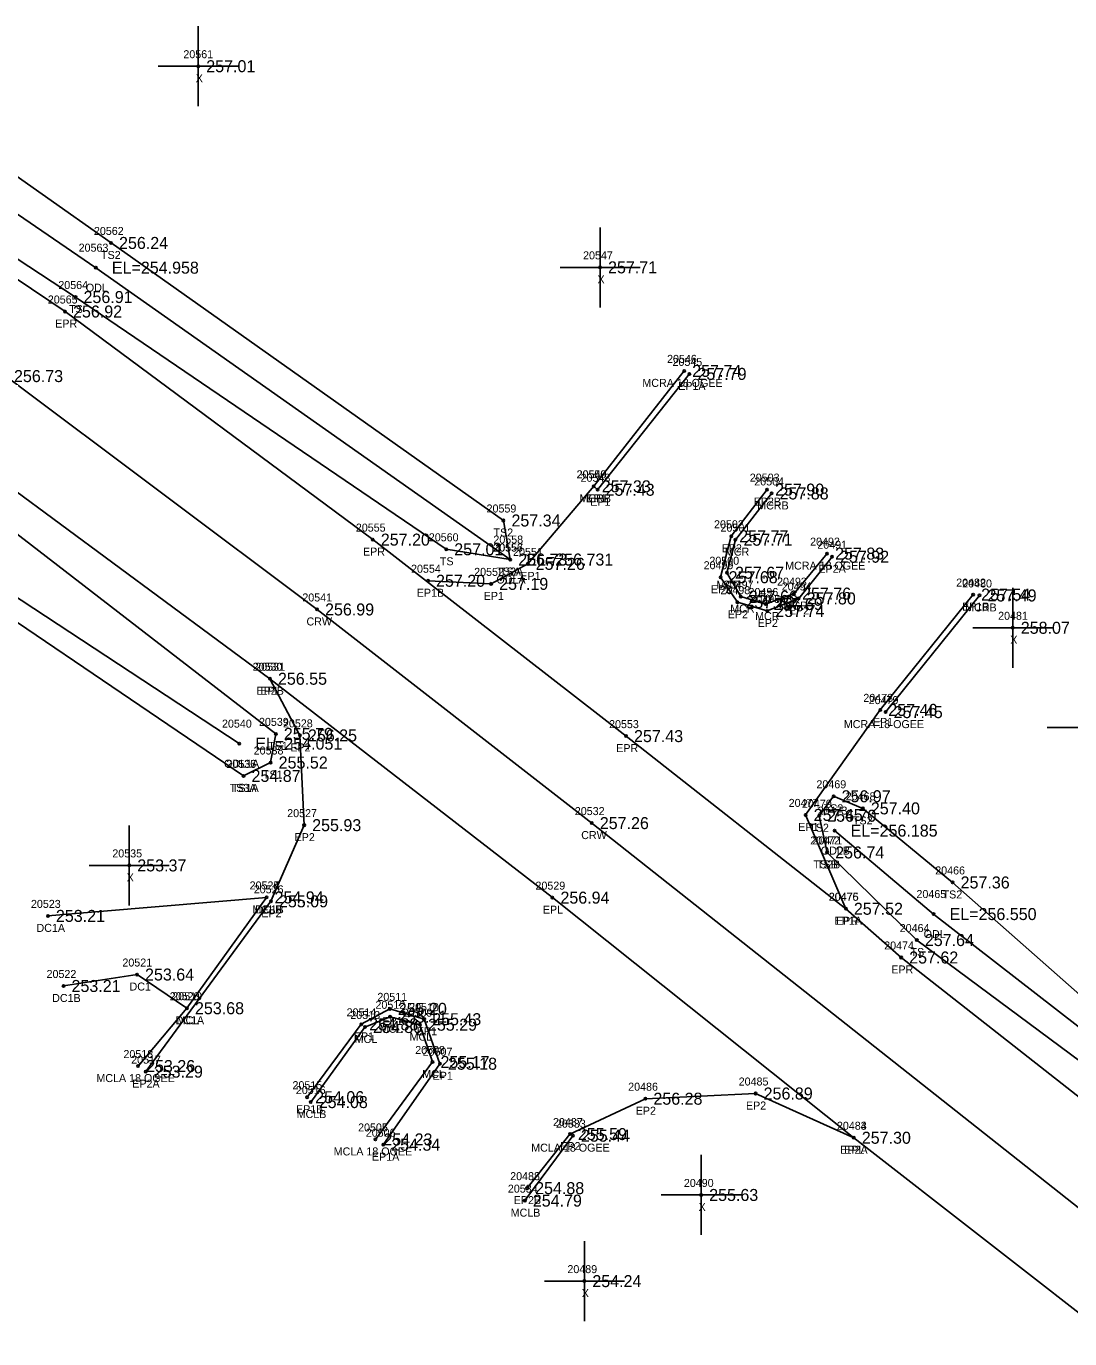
# Model space of a CAD drawing. Extents: x 1961330 to 1962287, y 800294 to 801079.
# Drawn here: x 1961401.6 to 1961532, y 800892.8 to 801056.9 of the extents above; entities that cross this region are included whole.
import ezdxf

# ---------------------------------------------------------------- set-up
doc = ezdxf.new("R2010")
doc.units = 0
for name, color, linetype in [('RD_DTM_BkLn1', 7, 'Continuous'), ('RD_DTM_BkLn2', 7, 'Continuous'), ('RD_DTM_BkLn_txCode', 7, 'Continuous'), ('RD_EX_Conc', 7, 'Continuous'), ('RD_EX_Conc_txCode', 7, 'Continuous'), ('RD_EX_H2O', 7, 'Continuous'), ('RD_EX_H2O_txCode', 7, 'Continuous'), ('RD_EX_Misc', 7, 'Continuous'), ('RD_EX_Misc_txCode', 7, 'Continuous'), ('RD_EX_Road', 7, 'Continuous'), ('RD_EX_Road_txCode', 7, 'Continuous'), ('RD_EX_TX_Conc_ELEV', 7, 'Continuous'), ('RD_EX_TX_H2O_ELEV', 7, 'Continuous'), ('RD_EX_TX_Misc_ELEV', 7, 'Continuous'), ('RD_EX_TX_Road_ELEV', 7, 'Continuous'), ('RD_HC_Survey_ELEV', 7, 'Continuous'), ('RD_HC_Survey_txCode', 7, 'Continuous'), ('RD_SMD_Locator', 7, 'Continuous')]:
    doc.layers.add(name, color=color, linetype=linetype)

msp = doc.modelspace()

# ---------------------------------------------------------------- linework, layer by layer
at = {"layer": 'RD_DTM_BkLn1'}
msp.add_lwpolyline([(1962257.08, 800334.72), (1962203.79, 800372.43), (1962164.31, 800399.58), (1962126.58, 800429.85), (1962084.5, 800463.37), (1962045.12, 800502.48), (1962010.49, 800530.36), (1961971.27, 800562.01), (1961931.18, 800594.14), (1961890.91, 800625.98), (1961844.41, 800662.62), (1961808.07, 800691.13), (1961729.11, 800753.37), (1961696.19, 800780.32), (1961667.25, 800802.66), (1961624.93, 800836.78), (1961588.01, 800866), (1961545.37, 800899.49), (1961472.25, 800957.29), (1961437.91, 800983.99), (1961399.03, 801013.16), (1961365.01, 801035.89)], dxfattribs=at)
at = {"layer": 'RD_DTM_BkLn2'}
for points in [[(1961462.06, 800990.23), (1961461.21, 800995.11), (1961412.16, 801029.8), (1961377.62, 801054.15)], [(1961462.06, 800990.23), (1961454.06, 800991.51), (1961407.72, 801023.04), (1961372.82, 801045.93)], [(1961428.72, 800963.19), (1961432.11, 800964.86), (1961432.76, 800968.44), (1961389.94, 801001.5), (1961357.87, 801022.45)], [(1961428.72, 800963.19), (1961383.97, 800993.54), (1961351.89, 801014.62)], [(1961558.68, 800914.76), (1961539.94, 800929.91), (1961517.35, 800949.87), (1961506.13, 800959.13), (1961502.47, 800960.64), (1961500.68, 800958.21), (1961501.67, 800953.62)], [(1961558.68, 800914.76), (1961535.94, 800925.53), (1961512.88, 800942.67), (1961501.67, 800953.62)]]:
    msp.add_lwpolyline(points, dxfattribs=at)
at = {"layer": 'RD_EX_Conc'}
for p, q in [((1961483.8, 801013.81), (1961472.49, 800999.38)), ((1961508.98, 800971.16), (1961520.71, 800985.74)), ((1961404.27, 800945.69), (1961431.6, 800948)), ((1961469.89, 800918.22), (1961463.88, 800910.1))]:
    msp.add_line(p, q, dxfattribs=at)
for points in [[(1961501.66, 800990.97), (1961497.53, 800985.97), (1961493.98, 800984.67), (1961490.87, 800985.6), (1961489.15, 800988.58), (1961490.21, 800992.71), (1961494.72, 800998.49)], [(1961415.54, 800926.92), (1961421.65, 800934.15), (1961431.6, 800948)], [(1961421.65, 800934.15), (1961415.41, 800938.36), (1961406.22, 800936.93)], [(1961445.2, 800917.75), (1961452.34, 800927.43), (1961450.77, 800932.09), (1961447.04, 800933.08), (1961443.9, 800931.8), (1961437.12, 800922.42)]]:
    msp.add_lwpolyline(points, dxfattribs=at)
at = {"layer": 'RD_EX_H2O'}
for points in [[(1961462.06, 800990.23), (1961410.26, 801026.71), (1961375.03, 801050.82)], [(1961428.19, 800967.22), (1961385.82, 800995.06), (1961353.46, 801018.5)], [(1961558.68, 800914.76), (1961538.2, 800927.85), (1961514.97, 800945.92), (1961502.6, 800956.35)]]:
    msp.add_lwpolyline(points, dxfattribs=at)
at = {"layer": 'RD_EX_Misc'}
for p, q in [((1961423.06, 801046.89), (1961423.06, 801056.89)), ((1961418.06, 801051.89), (1961428.06, 801051.89)), ((1961473.28, 801021.75), (1961473.28, 801031.75)), ((1961468.28, 801026.75), (1961478.28, 801026.75)), ((1961524.87, 800976.7), (1961524.87, 800986.7)), ((1961519.87, 800981.7), (1961529.87, 800981.7)), ((1961529.15, 800969.23), (1961539.15, 800969.23)), ((1961414.44, 800947), (1961414.44, 800957)), ((1961409.44, 800952), (1961419.44, 800952)), ((1961485.92, 800905.81), (1961485.92, 800915.81)), ((1961480.92, 800910.81), (1961490.92, 800910.81)), ((1961471.32, 800895.04), (1961471.32, 800905.04)), ((1961466.32, 800900.04), (1961476.32, 800900.04))]:
    msp.add_line(p, q, dxfattribs=at)
at = {"layer": 'RD_EX_Road'}
for points in [[(1961651.45, 800830.73), (1961641.14, 800839.02), (1961595.18, 800874.45), (1961552.9, 800907.54), (1961510.92, 800940.49), (1961504.01, 800946.58), (1961476.53, 800968.16), (1961444.88, 800992.72), (1961406.41, 801021.23), (1961370.69, 801045.26)], [(1961660.52, 800795.31), (1961637.49, 800813.67), (1961617.86, 800829), (1961581.48, 800857.91), (1961538.42, 800891.96), (1961505, 800917.96), (1961467.33, 800947.97), (1961432.02, 800975.33), (1961392.71, 801004.33), (1961360.06, 801026.78)], [(1961484.46, 801013.43), (1961472.97, 800998.95), (1961472.49, 800999.38), (1961464.24, 800989.69), (1961459.67, 800987.19), (1961451.78, 800987.58)], [(1961502.28, 800990.58), (1961498.11, 800985.37), (1961494.19, 800983.8), (1961490.45, 800984.9), (1961488.35, 800988.02), (1961489.68, 800993.14), (1961494.16, 800998.97)], [(1961504.01, 800946.58), (1961498.98, 800958.31), (1961508.31, 800971.44), (1961519.92, 800985.85)], [(1961416.5, 800926.22), (1961432.15, 800947.51), (1961436.3, 800957.03), (1961435.77, 800968.25), (1961432.02, 800975.33)], [(1961446.18, 800917.09), (1961453.27, 800927.21), (1961451.3, 800932.78), (1961447, 800934.07), (1961443.43, 800932.14), (1961436.67, 800923.03)], [(1961505, 800917.96), (1961492.73, 800923.49), (1961478.95, 800922.84), (1961469.51, 800918.42), (1961464.17, 800911.66)]]:
    msp.add_lwpolyline(points, dxfattribs=at)
at = {"layer": 'RD_SMD_Locator'}
for centre in [(1961423.06, 801051.89), (1961412.16, 801029.8), (1961410.26, 801026.71), (1961473.28, 801026.75), (1961407.72, 801023.04), (1961406.41, 801021.23), (1961483.8, 801013.81), (1961484.46, 801013.43), (1961472.49, 800999.38), (1961472.49, 800999.38), (1961472.97, 800998.95), (1961494.16, 800998.97), (1961494.72, 800998.49), (1961461.21, 800995.11), (1961444.88, 800992.72), (1961489.68, 800993.14), (1961490.21, 800992.71), (1961454.06, 800991.51), (1961462.06, 800990.23), (1961462.06, 800990.23), (1961462.06, 800990.23), (1961501.66, 800990.97), (1961502.28, 800990.58), (1961464.24, 800989.69), (1961489.15, 800988.58), (1961451.78, 800987.58), (1961459.67, 800987.19), (1961488.35, 800988.02), (1961490.87, 800985.6), (1961497.53, 800985.97), (1961498.11, 800985.37), (1961519.92, 800985.85), (1961520.71, 800985.74), (1961437.91, 800983.99), (1961490.45, 800984.9), (1961493.98, 800984.67), (1961494.19, 800983.8), (1961524.87, 800981.7), (1961432.02, 800975.33), (1961432.02, 800975.33), (1961508.31, 800971.44), (1961508.98, 800971.16), (1961428.19, 800967.22), (1961432.76, 800968.44), (1961435.77, 800968.25), (1961476.53, 800968.16), (1961432.11, 800964.86), (1961428.72, 800963.19), (1961428.72, 800963.19), (1961502.47, 800960.64), (1961506.13, 800959.13), (1961472.25, 800957.29), (1961498.98, 800958.31), (1961500.68, 800958.21), (1961436.3, 800957.03), (1961502.6, 800956.35), (1961501.67, 800953.62), (1961501.67, 800953.62), (1961414.44, 800952), (1961517.35, 800949.87), (1961431.6, 800948), (1961431.6, 800948), (1961432.15, 800947.51), (1961467.33, 800947.97), (1961504.01, 800946.58), (1961504.01, 800946.58), (1961514.97, 800945.92), (1961404.27, 800945.69), (1961512.88, 800942.67), (1961510.92, 800940.49), (1961415.41, 800938.36), (1961406.22, 800936.93), (1961421.65, 800934.15), (1961421.65, 800934.15), (1961447, 800934.07), (1961447.04, 800933.08), (1961451.3, 800932.78), (1961443.43, 800932.14), (1961443.9, 800931.8), (1961450.77, 800932.09), (1961415.54, 800926.92), (1961416.5, 800926.22), (1961452.34, 800927.43), (1961453.27, 800927.21), (1961436.67, 800923.03), (1961478.95, 800922.84), (1961492.73, 800923.49), (1961437.12, 800922.42), (1961469.51, 800918.42), (1961469.89, 800918.22), (1961505, 800917.96), (1961505, 800917.96), (1961445.2, 800917.75), (1961446.18, 800917.09), (1961464.17, 800911.66), (1961463.88, 800910.1), (1961485.92, 800910.81), (1961471.32, 800900.04)]:
    msp.add_circle(centre, 0.15, dxfattribs=at)

# ---------------------------------------------------------------- texts
at = {"layer": 'RD_DTM_BkLn_txCode'}
for s, p in [('20562', (1961410.02, 801030.8)), ('TS2', (1961410.91, 801027.8)), ('20564', (1961405.57, 801024.04)), ('TS', (1961406.92, 801021.04)), ('20559', (1961459.1, 800996.11)), ('20560', (1961451.88, 800992.51)), ('TS2', (1961459.97, 800993.11)), ('20556', (1961459.92, 800991.23)), ('20557', (1961459.95, 800991.23)), ('TS', (1961453.26, 800989.51)), ('TS2A', (1961460.33, 800988.23)), ('TSA', (1961460.78, 800988.23)), ('20539', (1961430.65, 800969.44)), ('TS1', (1961431.8, 800966.44)), ('20538', (1961429.99, 800965.86)), ('20536', (1961426.58, 800964.19)), ('20537', (1961426.6, 800964.19)), ('TS1', (1961431.15, 800962.86)), ('20469', (1961500.33, 800961.64)), ('TS3A', (1961426.99, 800961.19)), ('TS1A', (1961427.27, 800961.19)), ('20468', (1961503.99, 800960.13)), ('20470', (1961498.52, 800959.21)), ('TS2', (1961501.23, 800958.64)), ('TS2', (1961504.89, 800957.13)), ('TS2', (1961499.43, 800956.21)), ('20472', (1961499.55, 800954.62)), ('20471', (1961499.83, 800954.62)), ('TS2B', (1961499.95, 800951.62)), ('TSB', (1961500.4, 800951.62)), ('20466', (1961515.18, 800950.87)), ('TS2', (1961516.1, 800947.87)), ('20464', (1961510.74, 800943.67)), ('TS', (1961512.09, 800940.67))]:
    msp.add_text(s, height=1, dxfattribs=at).set_placement(p)
at = {"layer": 'RD_EX_Conc_txCode'}
for s, p in [('20546', (1961481.66, 801014.81)), ('MCRA 18 OGEE', (1961478.57, 801011.81)), ('20549', (1961470.37, 801000.38)), ('20504', (1961492.56, 800999.49)), ('MCRB', (1961470.71, 800997.38)), ('MCRB', (1961492.93, 800996.49)), ('20501', (1961488.34, 800993.71)), ('20492', (1961499.54, 800991.97)), ('20500', (1961486.95, 800989.58)), ('MCR', (1961488.89, 800990.71)), ('MCRA 18 OGEE', (1961496.42, 800988.97)), ('MCR', (1961487.83, 800986.58)), ('20497', (1961488.75, 800986.6)), ('20493', (1961495.41, 800986.97)), ('20480', (1961518.55, 800986.74)), ('20496', (1961491.84, 800985.67)), ('MCR', (1961489.56, 800983.6)), ('MCR', (1961492.66, 800982.67)), ('MCR', (1961496.21, 800983.97)), ('MCRB', (1961518.92, 800983.74)), ('20479', (1961506.86, 800972.16)), ('MCRA 18 OGEE', (1961503.75, 800969.16)), ('20524', (1961429.48, 800949)), ('20525', (1961429.48, 800949)), ('20523', (1961402.15, 800946.69)), ('MCLB', (1961429.83, 800946)), ('DC1B', (1961430.18, 800946)), ('DC1A', (1961402.84, 800943.69)), ('20521', (1961413.58, 800939.36)), ('20522', (1961404.1, 800937.93)), ('DC1', (1961414.47, 800936.36)), ('20520', (1961419.5, 800935.15)), ('20519', (1961419.82, 800935.15)), ('DC1B', (1961404.8, 800934.93)), ('20512', (1961445.21, 800934.08)), ('DC1A', (1961420.22, 800932.15)), ('MCL', (1961420.36, 800932.15)), ('20513', (1961442.07, 800932.8)), ('20509', (1961448.61, 800933.09)), ('MCL', (1961445.75, 800931.08)), ('MCL', (1961442.61, 800929.8)), ('MCL', (1961449.48, 800930.09)), ('20518', (1961413.71, 800927.92)), ('20508', (1961450.18, 800928.43)), ('MCL', (1961451.05, 800925.43)), ('MCLA 18 OGEE', (1961410.33, 800924.92)), ('20516', (1961435.26, 800923.42)), ('MCLB', (1961435.36, 800920.42)), ('20505', (1961443.04, 800918.75)), ('20533', (1961467.77, 800919.22)), ('MCLA 18 OGEE', (1961439.99, 800915.75)), ('MCLA 18 OGEE', (1961464.68, 800916.22)), ('20534', (1961461.76, 800911.1)), ('MCLB', (1961462.11, 800908.1))]:
    msp.add_text(s, height=1, dxfattribs=at).set_placement(p)
at = {"layer": 'RD_EX_H2O_txCode'}
for s, p in [('20563', (1961408.11, 801028.71)), ('ODL', (1961409.01, 801023.71)), ('20558', (1961459.95, 800992.23)), ('ODLA', (1961460.33, 800987.23)), ('20540', (1961426.03, 800969.22)), ('ODL1A', (1961426.29, 800964.22)), ('20473', (1961500.48, 800958.35)), ('ODLB', (1961500.88, 800953.35)), ('20465', (1961512.83, 800947.92)), ('ODL', (1961513.73, 800942.92))]:
    msp.add_text(s, height=1, dxfattribs=at).set_placement(p)
at = {"layer": 'RD_EX_Misc_txCode'}
for s, p in [('20561', (1961421.2, 801052.89)), ('X', (1961422.75, 801049.89)), ('20547', (1961471.16, 801027.75)), ('X', (1961472.96, 801024.75)), ('20481', (1961523.04, 800982.7)), ('X', (1961524.56, 800979.7)), ('20535', (1961412.32, 800953)), ('X', (1961414.12, 800950)), ('20490', (1961483.76, 800911.81)), ('X', (1961485.6, 800908.81)), ('20489', (1961469.2, 800901.04)), ('X', (1961471, 800898.04))]:
    msp.add_text(s, height=1, dxfattribs=at).set_placement(p)
at = {"layer": 'RD_EX_Road_txCode'}
for s, p in [('20565', (1961404.26, 801022.23)), ('EPR', (1961405.18, 801019.23)), ('20545', (1961482.34, 801014.43)), ('EP1A', (1961483.05, 801011.43)), ('20550', (1961470.34, 801000.38)), ('20548', (1961470.85, 800999.95)), ('20503', (1961492, 800999.97)), ('EP1', (1961471.57, 800997.38)), ('EP1', (1961472.05, 800996.95)), ('EP2B', (1961492.48, 800996.97)), ('20502', (1961487.53, 800994.14)), ('20555', (1961442.76, 800993.72)), ('EP2', (1961488.48, 800991.14)), ('20491', (1961500.44, 800991.58)), ('EPR', (1961443.65, 800990.72)), ('20551', (1961462.41, 800990.69)), ('20554', (1961449.66, 800988.58)), ('20552', (1961457.55, 800988.19)), ('EP1', (1961463.32, 800987.69)), ('20499', (1961486.23, 800989.02)), ('EP2A', (1961500.58, 800988.58)), ('EP2', (1961487.14, 800986.02)), ('20494', (1961495.99, 800986.37)), ('20482', (1961517.8, 800986.85)), ('EP1B', (1961450.38, 800985.58)), ('EP1', (1961458.74, 800985.19)), ('20498', (1961488.33, 800985.9)), ('20495', (1961492.07, 800984.8)), ('EP2', (1961489.25, 800982.9)), ('EP2', (1961496.9, 800983.37)), ('EP1B', (1961518.53, 800983.85)), ('EP2', (1961492.98, 800981.8)), ('20530', (1961429.86, 800976.33)), ('20531', (1961430.19, 800976.33)), ('EP2B', (1961430.34, 800973.33)), ('EPL', (1961430.82, 800973.33)), ('20478', (1961506.19, 800972.44)), ('20528', (1961433.65, 800969.25)), ('20553', (1961474.41, 800969.16)), ('EP1', (1961507.39, 800969.44)), ('EP2', (1961434.57, 800966.25)), ('EPR', (1961475.3, 800966.16)), ('20477', (1961496.86, 800959.31)), ('20527', (1961434.18, 800958.03)), ('EP2', (1961435.1, 800955.03)), ('EP1', (1961498.06, 800956.31)), ('20526', (1961430, 800948.51)), ('20529', (1961465.21, 800948.97)), ('20476', (1961501.86, 800947.58)), ('20475', (1961501.89, 800947.58)), ('EP2', (1961430.94, 800945.51)), ('EPL', (1961466.13, 800945.97)), ('EP1A', (1961502.6, 800944.58)), ('EPR', (1961502.78, 800944.58)), ('20474', (1961508.8, 800941.49)), ('EPR', (1961509.69, 800938.49)), ('20511', (1961445.45, 800935.07)), ('20510', (1961449.42, 800933.78)), ('20514', (1961441.6, 800933.14)), ('EP1', (1961446.08, 800932.07)), ('EP1', (1961450.38, 800930.78)), ('EP1', (1961442.51, 800930.14)), ('20517', (1961414.67, 800927.22)), ('20507', (1961451.11, 800928.21)), ('EP2A', (1961414.81, 800924.22)), ('20515', (1961434.84, 800924.03)), ('EP1', (1961452.35, 800925.21)), ('20486', (1961476.8, 800923.84)), ('20485', (1961490.61, 800924.49)), ('EP1B', (1961435.28, 800921.03)), ('EP2', (1961477.74, 800920.84)), ('EP2', (1961491.52, 800921.49)), ('20487', (1961467.4, 800919.42)), ('20483', (1961502.89, 800918.96)), ('20484', (1961502.89, 800918.96)), ('20506', (1961444, 800918.09)), ('EP2', (1961468.31, 800916.42)), ('EP2A', (1961503.31, 800915.96)), ('EPL', (1961503.8, 800915.96)), ('EP1A', (1961444.77, 800915.09)), ('20488', (1961462.05, 800912.66)), ('EP2B', (1961462.49, 800909.66))]:
    msp.add_text(s, height=1, dxfattribs=at).set_placement(p)
at = {"layer": 'RD_EX_TX_Conc_ELEV'}
for s, p in [('257.74', (1961484.8, 801013.06)), ('257.33', (1961473.49, 800998.63)), ('257.88', (1961495.72, 800997.74)), ('257.71', (1961491.21, 800991.96)), ('257.83', (1961502.66, 800990.22)), ('257.67', (1961490.15, 800987.83)), ('257.66', (1961491.87, 800984.85)), ('257.69', (1961494.98, 800983.92)), ('257.76', (1961498.53, 800985.22)), ('257.49', (1961521.71, 800984.99)), ('257.45', (1961509.98, 800970.41)), ('254.94', (1961432.6, 800947.25)), ('254.94', (1961432.6, 800947.25)), ('253.21', (1961405.27, 800944.94)), ('253.64', (1961416.41, 800937.61)), ('253.21', (1961407.22, 800936.18)), ('253.68', (1961422.65, 800933.4)), ('253.68', (1961422.65, 800933.4)), ('255.11', (1961448.04, 800932.33)), ('255.29', (1961451.77, 800931.34)), ('254.80', (1961444.9, 800931.05)), ('255.17', (1961453.34, 800926.68)), ('253.26', (1961416.54, 800926.17)), ('254.08', (1961438.12, 800921.67)), ('254.23', (1961446.2, 800917)), ('255.44', (1961470.89, 800917.47)), ('254.79', (1961464.88, 800909.35))]:
    msp.add_text(s, height=1.5, dxfattribs=at).set_placement(p)
at = {"layer": 'RD_EX_TX_H2O_ELEV'}
for s, p in [('EL=254.958', (1961412.26, 801025.96)), ('EL=256.731', (1961464.06, 800989.48)), ('EL=254.051', (1961430.19, 800966.47)), ('EL=256.185', (1961504.6, 800955.6)), ('EL=256.550', (1961516.97, 800945.17))]:
    msp.add_text(s, height=1.5, dxfattribs=at).set_placement(p)
at = {"layer": 'RD_EX_TX_Misc_ELEV'}
for s, p in [('257.01', (1961424.06, 801051.14)), ('256.24', (1961413.16, 801029.05)), ('257.71', (1961474.28, 801026)), ('256.91', (1961408.72, 801022.29)), ('257.34', (1961462.21, 800994.36)), ('257.01', (1961455.06, 800990.76)), ('256.73', (1961463.06, 800989.48)), ('256.73', (1961463.06, 800989.48)), ('258.07', (1961525.87, 800980.95)), ('255.79', (1961433.76, 800967.69)), ('255.52', (1961433.11, 800964.11)), ('254.87', (1961429.72, 800962.44)), ('254.87', (1961429.72, 800962.44)), ('256.97', (1961503.47, 800959.89)), ('257.40', (1961507.13, 800958.38)), ('256.70', (1961501.68, 800957.46)), ('256.74', (1961502.67, 800952.87)), ('256.74', (1961502.67, 800952.87)), ('253.37', (1961415.44, 800951.25)), ('257.36', (1961518.35, 800949.12)), ('257.64', (1961513.88, 800941.92)), ('255.63', (1961486.92, 800910.06)), ('254.24', (1961472.32, 800899.29))]:
    msp.add_text(s, height=1.5, dxfattribs=at).set_placement(p)
at = {"layer": 'RD_EX_TX_Road_ELEV'}
for s, p in [('256.92', (1961407.41, 801020.48)), ('257.79', (1961485.46, 801012.68)), ('257.33', (1961473.49, 800998.63)), ('257.43', (1961473.97, 800998.2)), ('257.90', (1961495.16, 800998.22)), ('257.77', (1961490.68, 800992.39)), ('257.20', (1961445.88, 800991.97)), ('257.26', (1961465.24, 800988.94)), ('257.92', (1961503.28, 800989.83)), ('257.68', (1961489.35, 800987.27)), ('257.20', (1961452.78, 800986.83)), ('257.19', (1961460.67, 800986.44)), ('257.70', (1961491.45, 800984.15)), ('257.80', (1961499.11, 800984.62)), ('257.54', (1961520.92, 800985.1)), ('257.74', (1961495.19, 800983.05)), ('256.55', (1961433.02, 800974.58)), ('256.55', (1961433.02, 800974.58)), ('257.46', (1961509.31, 800970.69)), ('256.25', (1961436.77, 800967.5)), ('257.43', (1961477.53, 800967.41)), ('257.45', (1961499.98, 800957.56)), ('255.93', (1961437.3, 800956.28)), ('255.09', (1961433.15, 800946.76)), ('256.94', (1961468.33, 800947.22)), ('257.52', (1961505.01, 800945.83)), ('257.52', (1961505.01, 800945.83)), ('257.62', (1961511.92, 800939.74)), ('255.20', (1961448, 800933.32)), ('254.88', (1961444.43, 800931.39)), ('255.43', (1961452.3, 800932.03)), ('255.18', (1961454.27, 800926.46)), ('253.29', (1961417.5, 800925.47)), ('254.06', (1961437.67, 800922.28)), ('256.28', (1961479.95, 800922.09)), ('256.89', (1961493.73, 800922.74)), ('255.59', (1961470.51, 800917.67)), ('257.30', (1961506, 800917.21)), ('257.30', (1961506, 800917.21)), ('254.34', (1961447.18, 800916.34)), ('254.88', (1961465.17, 800910.91))]:
    msp.add_text(s, height=1.5, dxfattribs=at).set_placement(p)
at = {"layer": 'RD_HC_Survey_ELEV'}
for s, p in [('256.73', (1961400.03, 801012.41)), ('256.99', (1961438.91, 800983.24)), ('257.26', (1961473.25, 800956.54))]:
    msp.add_text(s, height=1.5, dxfattribs=at).set_placement(p)
at = {"layer": 'RD_HC_Survey_txCode'}
for s, p in [('20541', (1961436.07, 800984.99)), ('CRW', (1961436.59, 800981.99)), ('20532', (1961470.13, 800958.29)), ('CRW', (1961470.93, 800955.29))]:
    msp.add_text(s, height=1, dxfattribs=at).set_placement(p)

doc.saveas('drawing.dxf')
